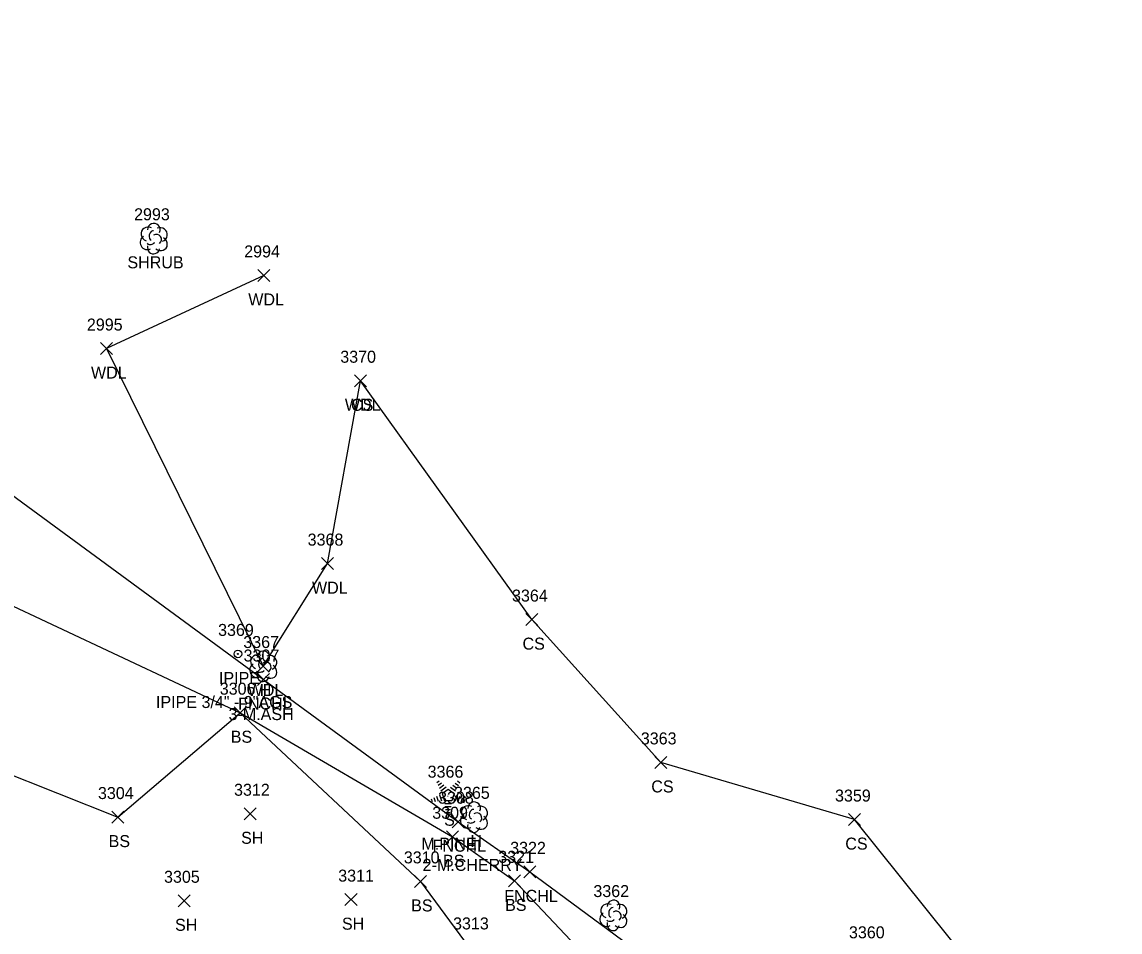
# Model space of a CAD drawing. Extents: x 1477930 to 1480780, y 774090 to 784647.
# Drawn here: x 1479682.6 to 1479865.5, y 775005.2 to 775156.7 of the extents above; entities that cross this region are included whole.
import ezdxf

# ---------------------------------------------------------------- set-up
doc = ezdxf.new("R2010")
doc.units = 0
for name, color, linetype in [('L_A', 7, 'Continuous'), ('L_C', 7, 'Continuous'), ('L_I', 7, 'Continuous'), ('L_TIC', 7, 'Continuous'), ('LAWA', 7, 'Continuous'), ('LELB', 7, 'Continuous'), ('LFNC', 7, 'Continuous'), ('LSH', 7, 'Continuous'), ('LTC', 7, 'Continuous'), ('LTD', 7, 'Continuous'), ('M_A', 7, 'Continuous'), ('M_C', 7, 'Continuous'), ('M_I', 7, 'Continuous'), ('MPIP', 7, 'Continuous')]:
    doc.layers.add(name, color=color, linetype=linetype)

msp = doc.modelspace()

# ---------------------------------------------------------------- linework, layer by layer
at = {"layer": 'L_TIC'}
for points in [[(1479721.85, 775113.5), (1479723.85, 775115.5)], [(1479723.85, 775113.5), (1479721.85, 775115.5)], [(1479695.65, 775101.32), (1479697.65, 775103.32)], [(1479697.65, 775101.32), (1479695.65, 775103.32)], [(1479737.94, 775095.96), (1479739.94, 775097.96)], [(1479739.94, 775095.96), (1479737.94, 775097.96)], [(1479737.94, 775095.96), (1479739.94, 775097.96)], [(1479739.94, 775095.96), (1479737.94, 775097.96)], [(1479732.46, 775065.51), (1479734.46, 775067.51)], [(1479734.46, 775065.51), (1479732.46, 775067.51)], [(1479766.51, 775056.19), (1479768.51, 775058.19)], [(1479768.51, 775056.19), (1479766.51, 775058.19)], [(1479721.75, 775048.46), (1479723.75, 775050.46)], [(1479723.75, 775048.46), (1479721.75, 775050.46)], [(1479721.83, 775046.21), (1479723.83, 775048.21)], [(1479723.83, 775046.21), (1479721.83, 775048.21)], [(1479717.91, 775040.69), (1479719.91, 775042.69)], [(1479719.91, 775040.69), (1479717.91, 775042.69)], [(1479717.91, 775040.69), (1479719.91, 775042.69)], [(1479719.91, 775040.69), (1479717.91, 775042.69)], [(1479787.96, 775032.41), (1479789.96, 775034.41)], [(1479789.96, 775032.41), (1479787.96, 775034.41)], [(1479697.57, 775023.31), (1479699.57, 775025.31)], [(1479699.57, 775023.31), (1479697.57, 775025.31)], [(1479719.6, 775023.86), (1479721.6, 775025.86)], [(1479721.6, 775023.86), (1479719.6, 775025.86)], [(1479754.21, 775022.54), (1479756.21, 775024.54)], [(1479756.21, 775022.54), (1479754.21, 775024.54)], [(1479820.27, 775022.89), (1479822.27, 775024.89)], [(1479822.27, 775022.89), (1479820.27, 775024.89)], [(1479753.26, 775020.03), (1479755.26, 775022.03)], [(1479755.26, 775020.03), (1479753.26, 775022.03)], [(1479766.15, 775014.19), (1479768.15, 775016.19)], [(1479768.15, 775014.19), (1479766.15, 775016.19)], [(1479747.96, 775012.6), (1479749.96, 775014.6)], [(1479749.96, 775012.6), (1479747.96, 775014.6)], [(1479763.61, 775012.69), (1479765.61, 775014.69)], [(1479765.61, 775012.69), (1479763.61, 775014.69)], [(1479708.58, 775009.37), (1479710.58, 775011.37)], [(1479710.58, 775009.37), (1479708.58, 775011.37)], [(1479736.38, 775009.56), (1479738.38, 775011.56)], [(1479738.38, 775009.56), (1479736.38, 775011.56)]]:
    msp.add_lwpolyline(points, dxfattribs=at)
at = {"layer": 'LAWA'}
msp.add_lwpolyline([(1479722.85, 775114.5), (1479696.65, 775102.32), (1479722.75, 775049.46), (1479733.46, 775066.51), (1479738.94, 775096.96)], dxfattribs=at)
at = {"layer": 'LELB'}
for points in [[(1479852.61, 774954.17), (1479865.47, 774968.61), (1479841.07, 774999.2), (1479821.27, 775023.89), (1479788.96, 775033.41), (1479767.51, 775057.19), (1479738.94, 775096.96)], [(1479643.43, 775043.81), (1479621.65, 775068.67), (1479633.5, 775077.11), (1479649.67, 775076.19), (1479678.22, 775060.75), (1479718.91, 775041.69), (1479754.26, 775021.03), (1479764.61, 775013.69), (1479779.59, 774997.82), (1479805.7, 774976.93)], [(1479668.33, 775036.3), (1479698.57, 775024.31), (1479718.91, 775041.69), (1479748.96, 775013.6), (1479757.07, 775002.6), (1479740.47, 774996.88), (1479735.8, 774983.7), (1479755.88, 774968.41), (1479775.22, 774977.03), (1479774.74, 774993.55), (1479805.7, 774976.93), (1479821.61, 774966.07), (1479839.92, 774951.74)]]:
    msp.add_lwpolyline(points, dxfattribs=at)
at = {"layer": 'LFNC'}
msp.add_lwpolyline([(1479575.18, 775156.7), (1479581.47, 775151.49), (1479610.54, 775129.98), (1479635.93, 775111.06), (1479670.34, 775085.66), (1479722.83, 775047.21), (1479755.21, 775023.54), (1479767.15, 775015.19), (1479810.87, 774982.94), (1479827.31, 774970.66), (1479838.7, 774961.65), (1479841.69, 774958.43)], dxfattribs=at)
at = {"layer": 'LSH'}
msp.add_line((1479704.51, 775120.68), (1479704.51, 775120.68), dxfattribs=at)
msp.add_line((1479704.51, 775120.68), (1479704.51, 775120.68), dxfattribs=at)
msp.add_arc((1479704.55, 775122.11), 1.05, 335.5272, 180.9563, dxfattribs=at)
for centre, major_axis, ratio, start_param, end_param in [((1479703.71, 775121.35), (1.21, -0.51), 0.895232, 1.570796, 4.712389), ((1479705.55, 775121.26), (-1.14, -0.48), 0.949671, 1.570796, 4.712389), ((1479703.42, 775119.97), (0.58, -1.04), 0.959034, 3.141593, 6.283185), ((1479704.3, 775121.14), (-0.208, -0.792), 0.645439, 3.141593, 6.283185), ((1479705.01, 775120.51), (-0.5, 0.667), 0.989748, 3.141593, 6.283185), ((1479705.51, 775119.85), (-1.09, 0.79), 0.841452, 1.570796, 4.712389), ((1479704.51, 775119.18), (0.26, 1.06), 0.942809, 1.570796, 4.712389), ((1479704.05, 775119.93), (-0.625, -0.083), 0.423636, 0, 3.141593)]:
    msp.add_ellipse(centre, major_axis=major_axis, ratio=ratio, start_param=start_param, end_param=end_param, dxfattribs=at)
at = {"layer": 'LTC'}
for p, q in [((1479751.7, 775030.08), (1479752.05, 775030.34)), ((1479751.91, 775029.62), (1479752.44, 775030)), ((1479752.12, 775029.15), (1479752.82, 775029.66)), ((1479752.33, 775028.68), (1479753.21, 775029.32)), ((1479752.55, 775028.23), (1479753.56, 775028.96)), ((1479753.56, 775028.96), (1479754.56, 775028.24)), ((1479753.98, 775029.28), (1479754.79, 775028.69)), ((1479754.35, 775029.62), (1479755.03, 775029.13)), ((1479754.73, 775029.97), (1479755.28, 775029.57)), ((1479755.1, 775030.32), (1479755.52, 775030.02)), ((1479750.73, 775027.36), (1479750.88, 775026.89)), ((1479751.19, 775027.58), (1479751.4, 775026.93)), ((1479751.64, 775027.79), (1479751.91, 775026.96)), ((1479752.1, 775028.01), (1479752.43, 775026.99)), ((1479752.55, 775028.23), (1479752.94, 775027.04)), ((1479754.17, 775027.04), (1479752.94, 775027.04)), ((1479754.56, 775028.24), (1479754.17, 775027.04)), ((1479755, 775027.97), (1479754.66, 775026.93)), ((1479755.44, 775027.72), (1479755.16, 775026.83)), ((1479755.89, 775027.47), (1479755.65, 775026.74)), ((1479756.33, 775027.22), (1479756.14, 775026.64)), ((1479754.13, 775026.54), (1479752.99, 775026.54)), ((1479754.05, 775026.04), (1479753.06, 775026.04)), ((1479753.96, 775025.54), (1479753.13, 775025.54)), ((1479753.88, 775025.04), (1479753.2, 775025.04))]:
    msp.add_line(p, q, dxfattribs=at)
at = {"layer": 'LTD'}
for p, q in [((1479722.75, 775049.46), (1479722.75, 775049.46)), ((1479722.75, 775049.46), (1479722.75, 775049.46)), ((1479757.84, 775024.35), (1479757.84, 775024.35)), ((1479757.84, 775024.35), (1479757.84, 775024.35)), ((1479781.06, 775007.99), (1479781.06, 775007.99)), ((1479781.06, 775007.99), (1479781.06, 775007.99))]:
    msp.add_line(p, q, dxfattribs=at)
for centre in [(1479722.79, 775050.89), (1479757.89, 775025.78), (1479781.1, 775009.42)]:
    msp.add_arc(centre, 1.05, 335.5272, 180.9563, dxfattribs=at)
for centre, major_axis, ratio, start_param, end_param in [((1479721.95, 775050.12), (1.21, -0.51), 0.895232, 1.570796, 4.712389), ((1479722.54, 775049.92), (-0.208, -0.792), 0.645439, 3.141593, 6.283185), ((1479723.79, 775050.04), (-1.14, -0.48), 0.949671, 1.570796, 4.712389), ((1479721.66, 775048.75), (0.58, -1.04), 0.959034, 3.141593, 6.283185), ((1479723.25, 775049.29), (-0.5, 0.667), 0.989748, 3.141593, 6.283185), ((1479723.75, 775048.63), (-1.09, 0.79), 0.841452, 1.570796, 4.712389), ((1479722.75, 775047.96), (0.26, 1.06), 0.942809, 1.570796, 4.712389), ((1479722.29, 775048.71), (-0.625, -0.083), 0.423636, 0, 3.141593), ((1479757.05, 775025.01), (1.21, -0.51), 0.895232, 1.570796, 4.712389), ((1479757.64, 775024.8), (-0.208, -0.792), 0.645439, 3.141593, 6.283185), ((1479758.89, 775024.93), (-1.14, -0.48), 0.949671, 1.570796, 4.712389), ((1479756.76, 775023.64), (0.58, -1.04), 0.959034, 3.141593, 6.283185), ((1479757.39, 775023.6), (-0.625, -0.083), 0.423636, 0, 3.141593), ((1479758.34, 775024.18), (-0.5, 0.667), 0.989748, 3.141593, 6.283185), ((1479758.84, 775023.51), (-1.09, 0.79), 0.841452, 1.570796, 4.712389), ((1479757.84, 775022.85), (0.26, 1.06), 0.942809, 1.570796, 4.712389), ((1479780.27, 775008.65), (1.21, -0.51), 0.895232, 1.570796, 4.712389), ((1479780.85, 775008.44), (-0.208, -0.792), 0.645439, 3.141593, 6.283185), ((1479781.56, 775007.82), (-0.5, 0.667), 0.989748, 3.141593, 6.283185), ((1479782.1, 775008.57), (-1.14, -0.48), 0.949671, 1.570796, 4.712389), ((1479779.97, 775007.28), (0.58, -1.04), 0.959034, 3.141593, 6.283185), ((1479780.6, 775007.24), (-0.625, -0.083), 0.423636, 0, 3.141593), ((1479782.06, 775007.15), (-1.09, 0.79), 0.841452, 1.570796, 4.712389), ((1479781.06, 775006.49), (0.26, 1.06), 0.942809, 1.570796, 4.712389)]:
    msp.add_ellipse(centre, major_axis=major_axis, ratio=ratio, start_param=start_param, end_param=end_param, dxfattribs=at)
at = {"layer": 'MPIP'}
for radius in [0.625, 0.0833]:
    msp.add_circle((1479718.55, 775051.47), radius, dxfattribs=at)

# ---------------------------------------------------------------- texts
at = {"layer": 'L_A'}
for s, p in [('SHRUB', (1479700.14, 775115.68)), ('WDL', (1479720.27, 775109.5)), ('WDL', (1479694.07, 775097.32)), ('WDL', (1479736.36, 775091.96)), ('CS', (1479737.38, 775091.96)), ('WDL', (1479730.88, 775061.51)), ('CS', (1479765.95, 775052.19)), ('WDL', (1479720.16, 775044.46)), ('H', (1479722.18, 775044.46)), ('FNCHL', (1479718.58, 775042.21)), ('BS', (1479717.35, 775036.69)), ('BS', (1479717.35, 775036.69)), ('CS', (1479787.4, 775028.41)), ('S', (1479752.89, 775022.87)), ('SH', (1479719.08, 775019.86)), ('BS', (1479697.01, 775019.31)), ('FNCHL', (1479750.96, 775018.54)), ('H', (1479757.28, 775019.35)), ('CS', (1479819.71, 775018.89)), ('BS', (1479752.7, 775016.03)), ('BS', (1479747.4, 775008.6)), ('FNCHL', (1479762.9, 775010.19)), ('BS', (1479763.05, 775008.69)), ('SH', (1479708.07, 775005.37)), ('SH', (1479735.87, 775005.56))]:
    msp.add_text(s, height=2, dxfattribs=at).set_placement(p)
at = {"layer": 'L_C'}
for s, p in [('3-M.ASH', (1479716.98, 775040.46)), ('M.PINE', (1479749.11, 775018.87)), ('2-M.CHERRY', (1479749.31, 775015.35))]:
    msp.add_text(s, height=2, dxfattribs=at).set_placement(p)
at = {"layer": 'L_I'}
for s, p in [('2993', (1479701.25, 775123.68)), ('2994', (1479719.59, 775117.5)), ('2995', (1479693.39, 775105.32)), ('3370', (1479735.59, 775099.96)), ('3370', (1479735.59, 775099.96)), ('3368', (1479730.16, 775069.51)), ('3364', (1479764.2, 775060.19)), ('3367', (1479719.44, 775052.46)), ('3367', (1479719.44, 775052.46)), ('3307', (1479719.49, 775050.21)), ('3306', (1479715.52, 775044.69)), ('3306', (1479715.52, 775044.69)), ('3363', (1479785.65, 775036.41)), ('3366', (1479750.14, 775030.87)), ('3304', (1479695.23, 775027.31)), ('3312', (1479717.9, 775027.86)), ('3365', (1479754.54, 775027.35)), ('3359', (1479818, 775026.89)), ('3308', (1479751.88, 775026.54)), ('3309', (1479750.91, 775024.03)), ('3322', (1479763.89, 775018.19)), ('3310', (1479746.18, 775016.6)), ('3321', (1479761.91, 775016.69)), ('3305', (1479706.24, 775013.37)), ('3311', (1479735.25, 775013.56)), ('3362', (1479777.75, 775010.99)), ('3313', (1479754.38, 775005.6)), ('3360', (1479820.32, 775004.12))]:
    msp.add_text(s, height=2, dxfattribs=at).set_placement(p)
at = {"layer": 'LTC'}
msp.add_text('.', height=1.04, rotation=270, dxfattribs=at).set_placement((1479753.45, 775027.98))
at = {"layer": 'M_A'}
msp.add_text('IPIPE', height=2, dxfattribs=at).set_placement((1479715.39, 775046.47))
at = {"layer": 'M_C'}
msp.add_text('IPIPE 3/4" - 9"AGS', height=2, dxfattribs=at).set_placement((1479704.9, 775042.47))
at = {"layer": 'M_I'}
msp.add_text('3369', height=2, dxfattribs=at).set_placement((1479715.24, 775054.47))

doc.saveas('drawing.dxf')
